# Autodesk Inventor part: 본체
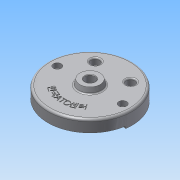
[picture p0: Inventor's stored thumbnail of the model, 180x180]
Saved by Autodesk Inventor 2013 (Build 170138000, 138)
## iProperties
Created: 2015-06
Part Number: 본체
Material: 알루미늄 6061
Document SubType Name: Modeling
Designer: Administrator
Density: 2.71 g/cm^3
Mass: 1070.99 g
Surface Area: 1034.49 cm^2
Volume: 395.201 cm^3
Author: Administrator
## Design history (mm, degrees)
sketch "스케치1"
  geometry: C1 r 95 at (0, 0); C2 r 90 at (0, 0); 1 further point
  constraints: 2 centre point, 2 coincident
  dimensions: "d0" = 190 diameter of C1; "d2" = 180 diameter of C2
extrude "돌출1" new body sketch "스케치1" distance "d3" = 32; taper "d4" = 0 deg
extrude "돌출2" cut sketch "스케치1" distance "d5" = 18; taper "d6" = 0 deg
sketch "스케치2"
  geometry: L1 (-38.833, 16)-(-88.566, 16); L2 (38.833, 16)-(88.566, 16); A1 r 90 centre (0, 0) between (-88.566, 16) and (88.566, 16); A2 r 42 centre (0, 0) between (-38.833, 16) and (38.833, 16)
  constraints: 4 end point, 4 point on circle, 2 centre point, 1 coincident, 1 collinear, 1 horizontal, 1 point on line
  dimensions: "d7" = 84 diameter of A2; "d9" = 16 distance from line of A1.centre L1
extrude "돌출3" cut sketch "스케치2" distance "d10" = 25; taper "d11" = 0 deg
sketch "스케치3"
  geometry: C1 r 35 at (0, 0); A1 r 42 centre (0, 0) between (38.833, 16) and (-38.833, 16) reference
  constraints: 1 centre point, 1 coincident
  dimensions: "d12" = 70 diameter of C1
extrude "돌출4" join sketch "스케치3" distance "d14" = 10; taper "d15" = -10 deg
sketch "스케치4"
  geometry: C1 r 35 at (0, 0) reference; C2 r 9 at (-74, 0); C3 r 9 at (74, 0)
  constraints: 2 centre point, 2 horizontal alignment
  dimensions: "d16" = 148 distance of C3.centre C2.centre; "d18" = 74 distance of C1.centre C2.centre; "d19" = 18 diameter of C2; "d20" = 18 diameter of C3
extrude "돌출5" join sketch "스케치4" stored distance "d21" = 10; taper "d22" = 0 deg
sketch "스케치5"
  geometry: L1 (-89.124, -12.526)-(-94.075, -13.221); L2 (94.075, -13.221)-(89.124, -12.526); A1 r 90 centre (0, 0) between (-89.124, -12.526) and (89.124, -12.526) reference; A2 r 95 centre (0, 0) between (-95, 0) and (95, 0) reference
  constraints: 6 point on circle, 4 end point, 2 horizontal alignment, 2 point on line
  dimensions: "d23" = 8 deg dimension on A1.centre L1.end A2.start; "d24" = 8 deg dimension on A1.centre L2.start A2.end
extrude "돌출6" cut sketch "스케치5" distance "d25" = 5; taper "d26" = 0 deg
sketch "스케치6"
  geometry: C1 r 15 at (-40, 52); C2 r 15 at (40, 52); A1 r 42 centre (0, 0) between (38.833, 16) and (-38.833, 16) reference
  constraints: 2 centre point, 1 horizontal alignment
  dimensions: "d27" = 30 diameter of C1; "d29" = 30 diameter of C2; "d30" = 80 distance of C2.centre C1.centre; "d31" = 52 vertical distance of A1.centre C2.centre; "d32" = 40 horizontal distance of A1.centre C2.centre
extrude "돌출7" join sketch "스케치6" stored distance "d33" = 5; taper "d34" = 0 deg
sketch "스케치7"
  geometry: C1 r 15 at (0, 0) reference; C2 r 15 at (80, 0) reference; 3 further points
  constraints: 2 coincident
hole "구멍1" sketch "스케치7" at (0, 0), (80, 0) diameter "d35" = 20; stored, may be unused: countersink angle "d39" = 90 deg, drill point angle "d41" = 118 deg; dims "d36" = 6, "d37" = 4, "d38" = 2, "d40" = 8
sketch "스케치8"
  geometry: L1 (-6, 13.748)-(-6, -13.748); L2 (6, 13.748)-(6, -13.748); L3 (66.252, 6)-(93.748, 6); L4 (66.252, -6)-(93.748, -6); A1 r 15 centre (0, 0) between (-6, 13.748) and (-6, -13.748) reference; A2 r 15 centre (80, 0) between (66.252, 6) and (93.748, 6) reference; 1 further point
  constraints: 8 end point, 8 point on circle, 4 parallel, 1 perpendicular, 1 vertical
  dimensions: "d51" = 12 distance between parallel lines of L1 L2; "d52" = 12 distance between parallel lines of L4 L3
extrude "돌출8" cut sketch "스케치8" distance "d53" = 3; taper "d54" = 0 deg
sketch "스케치9"
  geometry: C1 r 9 at (-74, 0) reference; C2 r 9 at (74, 0) reference; 2 further points
  constraints: 2 coincident
hole "구멍3" sketch "스케치9" at (-74, 0), (74, 0) diameter "d55" = 11; stored, may be unused: countersink angle "d59" = 90 deg, drill point angle "d61" = 118 deg; dims "d56" = 6, "d57" = 18, "d58" = 11, "d60" = 8
sketch "스케치10"
  geometry: C1 r 95 at (0, 0) reference; C2 r 26 at (0, 0)
  constraints: 1 centre point, 1 coincident
  dimensions: "d62" = 52 diameter of C2
extrude "돌출9" join sketch "스케치10" distance "d64" = 12; taper "d65" = -15 deg
hole "구멍2" diameter "d44" = 23; stored, may be unused: countersink angle "d48" = 90 deg, drill point angle "d50" = 118 deg; dims "d42" = 10, "d43" = 10, "d45" = 6, "d46" = 50, "d47" = 15, "d49" = 8
sketch "스케치11"
  geometry: L1 (-59, -19)-(-59, -14); L2 (-41, -14)-(-41, -19); L3 (41, -19)-(41, -14); L4 (59, -19)-(59, -14); C1 r 35 at (0, 0) reference; A1 r 59 centre (0, -19) between (-59, -19) and (59, -19); A2 r 41 centre (0, -19) between (-41, -19) and (41, -19); A3 r 9 centre (-50, -14) between (-41, -14) and (-59, -14); A4 r 9 centre (50, -14) between (59, -14) and (41, -14); 1 further point
  constraints: 8 end point, 8 point on circle, 7 horizontal alignment, 4 centre point, 4 vertical, 2 coincident, 2 tangent, 1 vertical alignment
  dimensions: "d66" = 41 radius of A2; "d68" = 59 radius of A1; "d69" = 19 distance of point (0, -19) C1.centre; "d70" = 5 distance of L4.start L4.end
extrude "돌출10" cut sketch "스케치11" distance "d72" = 7; taper "d73" = 0 deg
sketch "스케치12"
  geometry: C1 r 95 at (0, 0) reference; C2 r 68 at (0, 0)
  constraints: 1 centre point, 1 coincident, 1 other
  dimensions: "d74" = 136 diameter of C2
feature "엠보싱1" sketch "스케치12" dims "d76" = 0.5, "d77" = 0
fillet "모깎기1" dims "d78" = 10, "d79" = 5, "d80" = 0.3, "d81" = 1
fillet "모깎기2" dims "d82" = 3
chamfer "모따기1" distance "d83" = 1; stored, may be unused: second distance "d84" = 2, angle "d85" = 45 deg
fillet "모깎기3" dims "d86" = 3
node "솔리드1"
node "투영된 루프1"
